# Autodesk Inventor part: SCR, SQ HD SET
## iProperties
Category: Hardware
Title: SCR, SQ HD SET
Author: John Muchow
Keywords: Screw, Square Head Set
Revision Number: B
Shininess: 64.0
Angle Display Precision: 2
Document Length Units: 11272
Document Angle Units: 11286
Document Time Units: 11279
Document Mass Units: 11290
Document Length Units Precision: 3
Document Angle Units Precision: 2
Compacted: True
PropertySet Name: _Private Model Information
Created: 2002-10
Part Number: 108-00012-0038-16-0100
Engr Approved By: John M
Material: STEEL, MILD
Description: SCR, SQ HD SET
Document SubType Name: Modeling
Designer: John Muchow
Control State: 0
Master: False
Checked Out: False
PropertySet Name: Design Tracking Control
Density: 0.0
Volumn: 0.0
Area: 0.0
PropertySet Name: Model Information
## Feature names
1. Revolution1
2. Extrusion1
3. Chamfer1
4. Revolution2
